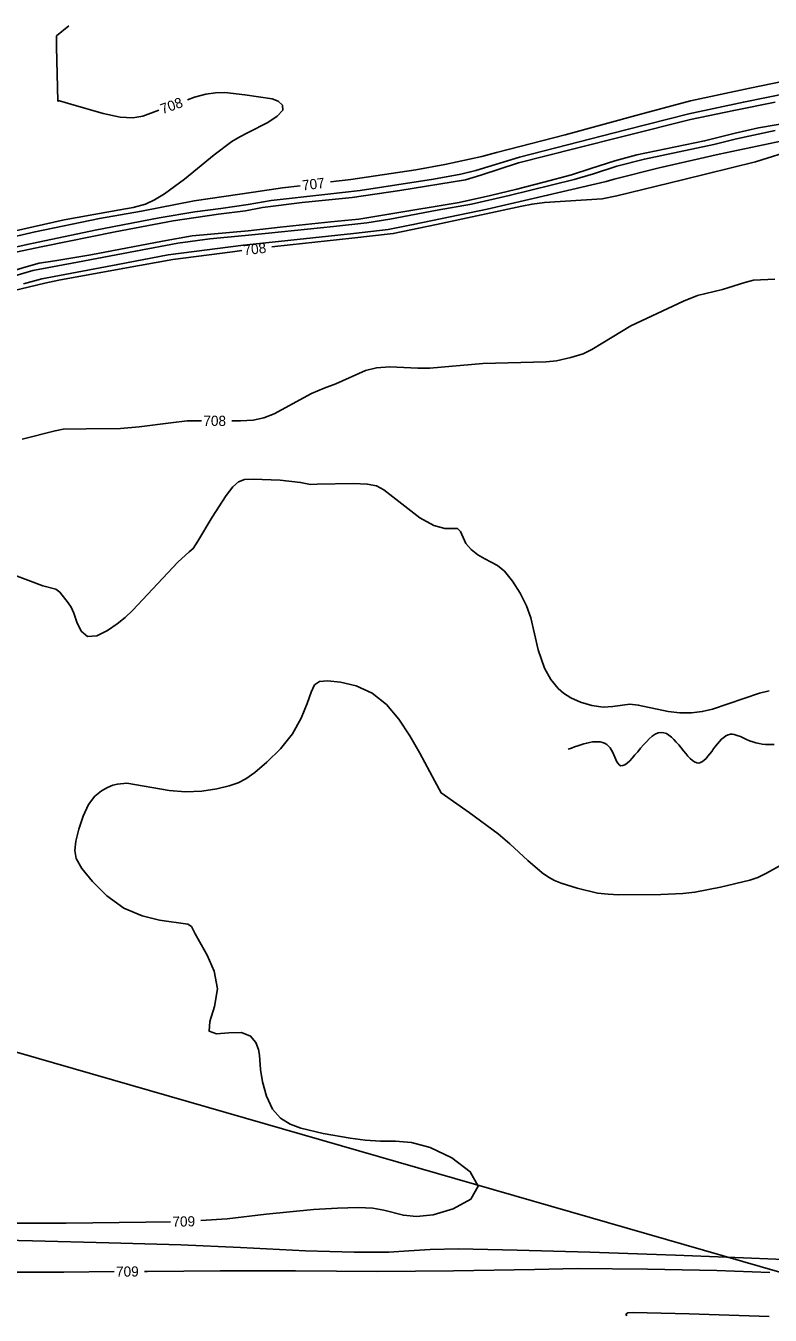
# Model space of a CAD drawing. Extents: x -468548933 to 3387700, y -306089263 to 1207014.
# Drawn here: x 1840637 to 1840930, y 538847 to 539354 of the extents above; entities that cross this region are included whole.
import ezdxf

# ---------------------------------------------------------------- set-up
doc = ezdxf.new("R2010")
doc.units = 0
for name, color, linetype in [('DT_X_Contour_Minor', 7, 'Continuous'), ('Level 19', 7, 'Continuous'), ('Level 56', 7, 'Continuous'), ('SC_Scratch1', 7, 'Continuous')]:
    doc.layers.add(name, color=color, linetype=linetype)

msp = doc.modelspace()

# ---------------------------------------------------------------- linework, layer by layer
at = {"layer": 'DT_X_Contour_Minor'}
for points in [[(1840654.27, 539354.12), (1840649.35, 539350.12), (1840649.33, 539345.87), (1840649.89, 539324.49), (1840650.31, 539324.63), (1840650.55, 539324.63), (1840654.99, 539323.33), (1840667.79, 539319.63), (1840674.42, 539318.2), (1840679.4, 539317.86), (1840683.4, 539318.54), (1840689.73, 539320.89)], [(1840618.54, 539263.67), (1840637.79, 539268.09), (1840664.56, 539273.66), (1840689.84, 539278.54), (1840703.88, 539280.87), (1840714.02, 539282.17), (1840724.81, 539283.75), (1840733.92, 539285.29), (1840755, 539287.72), (1840768.87, 539289.34), (1840797.81, 539293.75), (1840808.53, 539295.67), (1840814.5, 539297.11), (1840831.62, 539302.36), (1840855.06, 539308.38), (1840873.5, 539313.18), (1840898.33, 539319.49), (1840919.77, 539324.07), (1840928.88, 539325.89), (1840954.02, 539331.06), (1840966.44, 539333.22), (1840993.7, 539337.34), (1841006.71, 539339.49)], [(1840757.23, 539292.64), (1840765.22, 539293.63), (1840790.77, 539297.4), (1840802.25, 539299.54), (1840816.85, 539302.64), (1840822.55, 539304.28), (1840849.65, 539311.26), (1840878.82, 539319.22), (1840898.92, 539324.53), (1840922.25, 539329.55), (1840949.7, 539335.19)], [(1840701.01, 539324.99), (1840703.71, 539325.96), (1840708.13, 539327.17), (1840711.92, 539327.76), (1840715.62, 539327.82), (1840723.53, 539326.93), (1840734.23, 539325.41), (1840736.6, 539324.39), (1840738.35, 539322.86), (1840738.46, 539320.86), (1840736.28, 539318.49), (1840732.57, 539316.03), (1840724.82, 539312.06), (1840721.57, 539310.46), (1840718.35, 539308.58), (1840711.48, 539303.39), (1840699.73, 539293.81), (1840691.94, 539288.04), (1840687.94, 539285.57), (1840684.43, 539283.95), (1840679.6, 539282.58), (1840674.32, 539281.64), (1840652.47, 539277.8), (1840627.95, 539272.26)], [(1840630.95, 539264.45), (1840643.96, 539267.23), (1840672.54, 539273.07), (1840695.29, 539277.34), (1840713.15, 539279.97), (1840723.76, 539281.3), (1840730.53, 539282.58), (1840746.12, 539284.51), (1840765.76, 539286.55), (1840784.51, 539289.32), (1840810.31, 539293.5), (1840816.42, 539295.32), (1840831.29, 539300.16), (1840853.57, 539305.81), (1840873.39, 539310.85), (1840898.99, 539317.19), (1840915.97, 539320.82), (1840932.2, 539324.07)], [(1840952.69, 539318.55), (1840925.74, 539313.91), (1840916.46, 539311.79), (1840904.45, 539308.79), (1840877.84, 539303.35), (1840869.21, 539301.02), (1840859.69, 539297.94), (1840852.14, 539295.49), (1840841.15, 539292.6), (1840830.61, 539289.81), (1840820.19, 539287.29), (1840807.94, 539284.58), (1840780.21, 539279.94), (1840768.32, 539278), (1840757.33, 539276.91), (1840737.46, 539274.86), (1840724.77, 539273.43), (1840702.79, 539271.42), (1840691.14, 539269.4), (1840662.86, 539263.98), (1840648.79, 539261.65), (1840642.6, 539260.69), (1840637.51, 539259.3), (1840620.72, 539254.15)], [(1840932.21, 539312.9), (1840917.05, 539309.66), (1840908.13, 539307.43), (1840880.78, 539301.62), (1840869.87, 539298.84), (1840860.72, 539295.85), (1840853.1, 539293.62), (1840827.6, 539287.28), (1840812.75, 539283.92), (1840799.25, 539281.6), (1840780.54, 539278.02), (1840771.53, 539276.6), (1840758.43, 539275.16), (1840732.8, 539272.45), (1840723.62, 539271.57), (1840709.75, 539270.24), (1840697.16, 539268.52), (1840680.5, 539265.4), (1840657.65, 539261.13), (1840640.05, 539257.86), (1840629.43, 539254.62)], [(1840935.15, 539308.87), (1840910.25, 539303.6), (1840886.64, 539298.15), (1840868.84, 539293.73), (1840865.78, 539292.81), (1840842.66, 539287.39), (1840818.96, 539281.98), (1840789.8, 539275.89), (1840779.97, 539273.98), (1840766.34, 539272.39), (1840734.22, 539268.97), (1840723.03, 539267.8), (1840693.31, 539263.91), (1840673.51, 539260.2), (1840643.63, 539254.53), (1840636.34, 539252.58)], [(1840734.18, 539267.07), (1840741.35, 539267.92), (1840765.68, 539270.52), (1840781.96, 539272.34), (1840798.96, 539275.95), (1840832.56, 539283.17), (1840836.57, 539283.91), (1840841.52, 539284.51), (1840864.19, 539286.07), (1840869.98, 539287.21), (1840895.84, 539293.55), (1840924.54, 539300.52), (1840956.23, 539310.59)], [(1840614.59, 539266.99), (1840640.97, 539273.05), (1840666.28, 539278.22), (1840682.81, 539281.2), (1840703.62, 539285.22), (1840726.91, 539288.65), (1840738.33, 539290.29), (1840745.32, 539291.16)], [(1840613.46, 539245.3), (1840644.74, 539252.76), (1840650.34, 539254.05), (1840675.45, 539258.65), (1840695.2, 539262.18), (1840718.66, 539265.21), (1840722.27, 539265.64)], [(1840932.06, 539254.39), (1840923.77, 539253.93), (1840920.32, 539253.14), (1840911.46, 539250.34), (1840901.73, 539248), (1840896.17, 539245.68), (1840875.5, 539236.06), (1840864.41, 539229.38), (1840860.06, 539226.72), (1840856.73, 539225.05), (1840851.8, 539223.49), (1840846.23, 539222.27), (1840842.16, 539221.86), (1840817.17, 539221.19), (1840796.27, 539219.42), (1840791.63, 539219.42), (1840780.59, 539219.87), (1840775.37, 539219.54), (1840771.07, 539218.39), (1840759.37, 539213.25), (1840754.72, 539211.54), (1840749.77, 539209.45), (1840735.12, 539201.44), (1840730.98, 539199.81), (1840726.77, 539198.93), (1840721.83, 539198.57), (1840718.43, 539198.59)], [(1840706.43, 539198.64), (1840700.76, 539198.63), (1840694.34, 539197.78), (1840681.97, 539196.22), (1840674.56, 539195.66), (1840661.04, 539195.52), (1840652.01, 539195.3), (1840648.82, 539194.75), (1840635.93, 539191.42)], [(1840705.08, 539151.21), (1840710.62, 539160.75), (1840716.2, 539169.3), (1840718.8, 539172.65), (1840720.97, 539174.64), (1840723.37, 539175.51), (1840726.83, 539175.7), (1840737.45, 539175.3), (1840745.44, 539174.39), (1840749.39, 539173.52), (1840752, 539173.69), (1840766.28, 539173.95), (1840771.7, 539173.74), (1840775.4, 539173.04), (1840778.28, 539171.52), (1840792.42, 539160.5), (1840797.9, 539157.37), (1840802.18, 539156.29), (1840807.21, 539156.31), (1840808.37, 539155.06), (1840810.51, 539150.34), (1840812.59, 539147.96), (1840815.23, 539145.91), (1840817.98, 539144.31), (1840823.02, 539141.73), (1840825.75, 539139.39), (1840828.83, 539135.57), (1840831.9, 539130.78), (1840834.41, 539125.76), (1840836.02, 539121.09), (1840838.93, 539108.44), (1840841.48, 539101.29), (1840844.01, 539096.77), (1840846.89, 539093.25), (1840848.91, 539091.44), (1840851.77, 539089.64), (1840855.66, 539087.95), (1840860.11, 539086.62), (1840864.51, 539085.96), (1840868.38, 539086.13), (1840875.06, 539087.06), (1840878.34, 539086.77), (1840890.14, 539084.27), (1840894.79, 539083.76), (1840899.33, 539083.7), (1840903.54, 539084.2), (1840907.54, 539085.18), (1840926.12, 539091.5), (1840929.95, 539092.38)], [(1840631.19, 539138.53), (1840644.02, 539133.74), (1840649.09, 539132.4), (1840650.69, 539131.24), (1840654.03, 539126.97), (1840655.14, 539125.35), (1840656.26, 539122.9), (1840657.44, 539119.38), (1840659.05, 539115.86), (1840661.56, 539113.76), (1840665.22, 539114.06), (1840669.42, 539116.08), (1840673.32, 539118.72), (1840676.39, 539121.18), (1840679.24, 539123.91), (1840697.17, 539143.02), (1840701.61, 539147.01), (1840703.24, 539148.37), (1840705.08, 539151.21)], [(1840935.92, 539024.58), (1840928.88, 539020.58), (1840925.48, 539018.92), (1840922.3, 539017.79), (1840910.7, 539015.12), (1840900.64, 539013.1), (1840895.93, 539012.56), (1840887.3, 539012.19), (1840870.71, 539012.05), (1840866.5, 539012.28), (1840862.31, 539012.78), (1840854.34, 539014.64), (1840847.99, 539016.64), (1840845.44, 539017.66), (1840843.01, 539018.96), (1840840.49, 539020.71), (1840834.89, 539025.58), (1840827.88, 539032.1), (1840823.19, 539036.03), (1840811.77, 539044.46), (1840800.8, 539052.16), (1840798.35, 539056.75), (1840792.41, 539067.87), (1840788.44, 539074.63), (1840784.08, 539081.19), (1840779.21, 539086.98), (1840773.63, 539091.48), (1840767.33, 539094.34), (1840761.14, 539095.8), (1840756.07, 539096.26), (1840752.84, 539095.99), (1840750.95, 539094.68), (1840749.59, 539091.88), (1840748.03, 539087.35), (1840745.75, 539081.62), (1840742.31, 539075.44), (1840737.52, 539069.5), (1840732.2, 539064.3), (1840727.42, 539060.26), (1840723.89, 539057.68), (1840720.89, 539056.11), (1840717.36, 539054.96), (1840712.47, 539053.8), (1840706.54, 539052.86), (1840700.12, 539052.54), (1840693.77, 539053.09), (1840677.11, 539055.99), (1840673.37, 539055.66), (1840671.52, 539055.16), (1840669.44, 539054.33), (1840667.04, 539053.04), (1840664.48, 539050.94), (1840662.02, 539047.67), (1840659.87, 539043.07), (1840658.17, 539037.91), (1840657, 539033.19), (1840656.54, 539029.57), (1840657.19, 539026.34), (1840659.41, 539022.47), (1840663.5, 539017.28)], [(1840663.5, 539017.28), (1840669.16, 539011.65), (1840675.9, 539006.83), (1840683.14, 539003.74), (1840689.94, 539002.12), (1840701.04, 539000.52), (1840702.52, 538999.54), (1840704, 538996.69), (1840708.66, 538988.37), (1840711.49, 538982.02), (1840712.76, 538975), (1840711.63, 538968.05), (1840709.76, 538962.17), (1840709.47, 538958.42), (1840712.38, 538957.38), (1840717.28, 538957.8), (1840722.25, 538957.92), (1840725.78, 538956.46), (1840727.86, 538953.9), (1840728.88, 538951.2), (1840729.25, 538949), (1840729.67, 538943.33), (1840730.52, 538938.4), (1840732.07, 538932.77), (1840734.42, 538927.68), (1840737.58, 538924.09), (1840741.36, 538921.79), (1840745.51, 538920.28), (1840754.39, 538918.16), (1840764.98, 538916.29), (1840770.89, 538915.5), (1840776.87, 538915.09), (1840782.79, 538915.06), (1840789.13, 538914.6), (1840796.52, 538912.67), (1840805.01, 538908.58), (1840812.27, 538903.09), (1840815.41, 538897.33), (1840812.5, 538892.28), (1840805.56, 538888.41), (1840797.59, 538886.06), (1840791.02, 538885.41), (1840785.93, 538885.95), (1840778.17, 538887.98), (1840773.94, 538888.67), (1840768.12, 538888.97), (1840760.02, 538888.78), (1840750.5, 538888.2), (1840731.96, 538886.38), (1840716.55, 538884.56), (1840706.25, 538883.85)], [(1840694.26, 538883.39), (1840684.53, 538883.17), (1840653.2, 538882.84), (1840621.69, 538882.88)], [(1840612.34, 538876.51), (1840639.89, 538875.83), (1840670.01, 538875.03), (1840698.36, 538874.25), (1840721.78, 538873.3), (1840747.42, 538871.96), (1840766.49, 538871.45), (1840780.2, 538871.45), (1840788.09, 538871.9), (1840796.42, 538872.51), (1840807.57, 538872.72), (1840830.66, 538872.25), (1840859.31, 538871.45), (1840893.02, 538870.24), (1840919.79, 538869.2), (1840945.25, 538868.07)], [(1840684.07, 538863.84), (1840685.16, 538863.85), (1840713.8, 538864.13), (1840743.52, 538864), (1840775.71, 538863.85), (1840805.7, 538864.03), (1840837.48, 538864.61), (1840854.32, 538864.97), (1840881.94, 538864.74), (1840909.33, 538864.19), (1840930.09, 538863.35)], [(1840622.98, 538863.48), (1840652.3, 538863.58), (1840672.07, 538863.74)], [(1840929.9, 538846.14), (1840898.34, 538847.11), (1840876.34, 538847.69), (1840874.28, 538847.47), (1840873.49, 538846.96), (1840873.85, 538846.32)]]:
    msp.add_lwpolyline(points, dxfattribs=at)
at = {"layer": 'Level 56'}
msp.add_spline([(1840931.84, 539071.19), (1840930.89, 539071.17), (1840920.97, 539073.2), (1840914.67, 539075.24), (1840902.19, 539063.94), (1840887.38, 539075.99), (1840870.85, 539063.25), (1840867.31, 539069.87), (1840850.84, 539069.34)], degree=3, dxfattribs=at)
at = {"layer": 'SC_Scratch1'}
msp.add_lwpolyline([(1834448.38, 536360.46), (1835055.83, 534489.39), (1836664.2, 534206.16), (1839225.76, 534394.17), (1842361.7, 536308.3), (1842189.37, 536805.14), (1841581.79, 538676.58), (1840313.7, 539042.49), (1837357.67, 538260.17), (1834781.04, 538194.31), (1834403.13, 536496.43)], close=True, dxfattribs=at)

# ---------------------------------------------------------------- texts
at = {"layer": 'Level 19'}
for s, rotation, p in [('708', 19.8243, (1840691.11, 539319.29)), ('707', 7.076, (1840746.3, 539289.27)), ('708', 6.8182, (1840723.25, 539263.75)), ('708', 359.6628, (1840707.18, 539196.66)), ('709', 1.2834, (1840695.05, 538881.4)), ('709', 0.4698, (1840672.83, 538861.75))]:
    msp.add_text(s, height=4, rotation=rotation, dxfattribs=at).set_placement(p)

doc.saveas('drawing.dxf')
